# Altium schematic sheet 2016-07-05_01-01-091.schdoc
size 778 x 358 mm; SheetNumber: 1; SheetTotal: 1
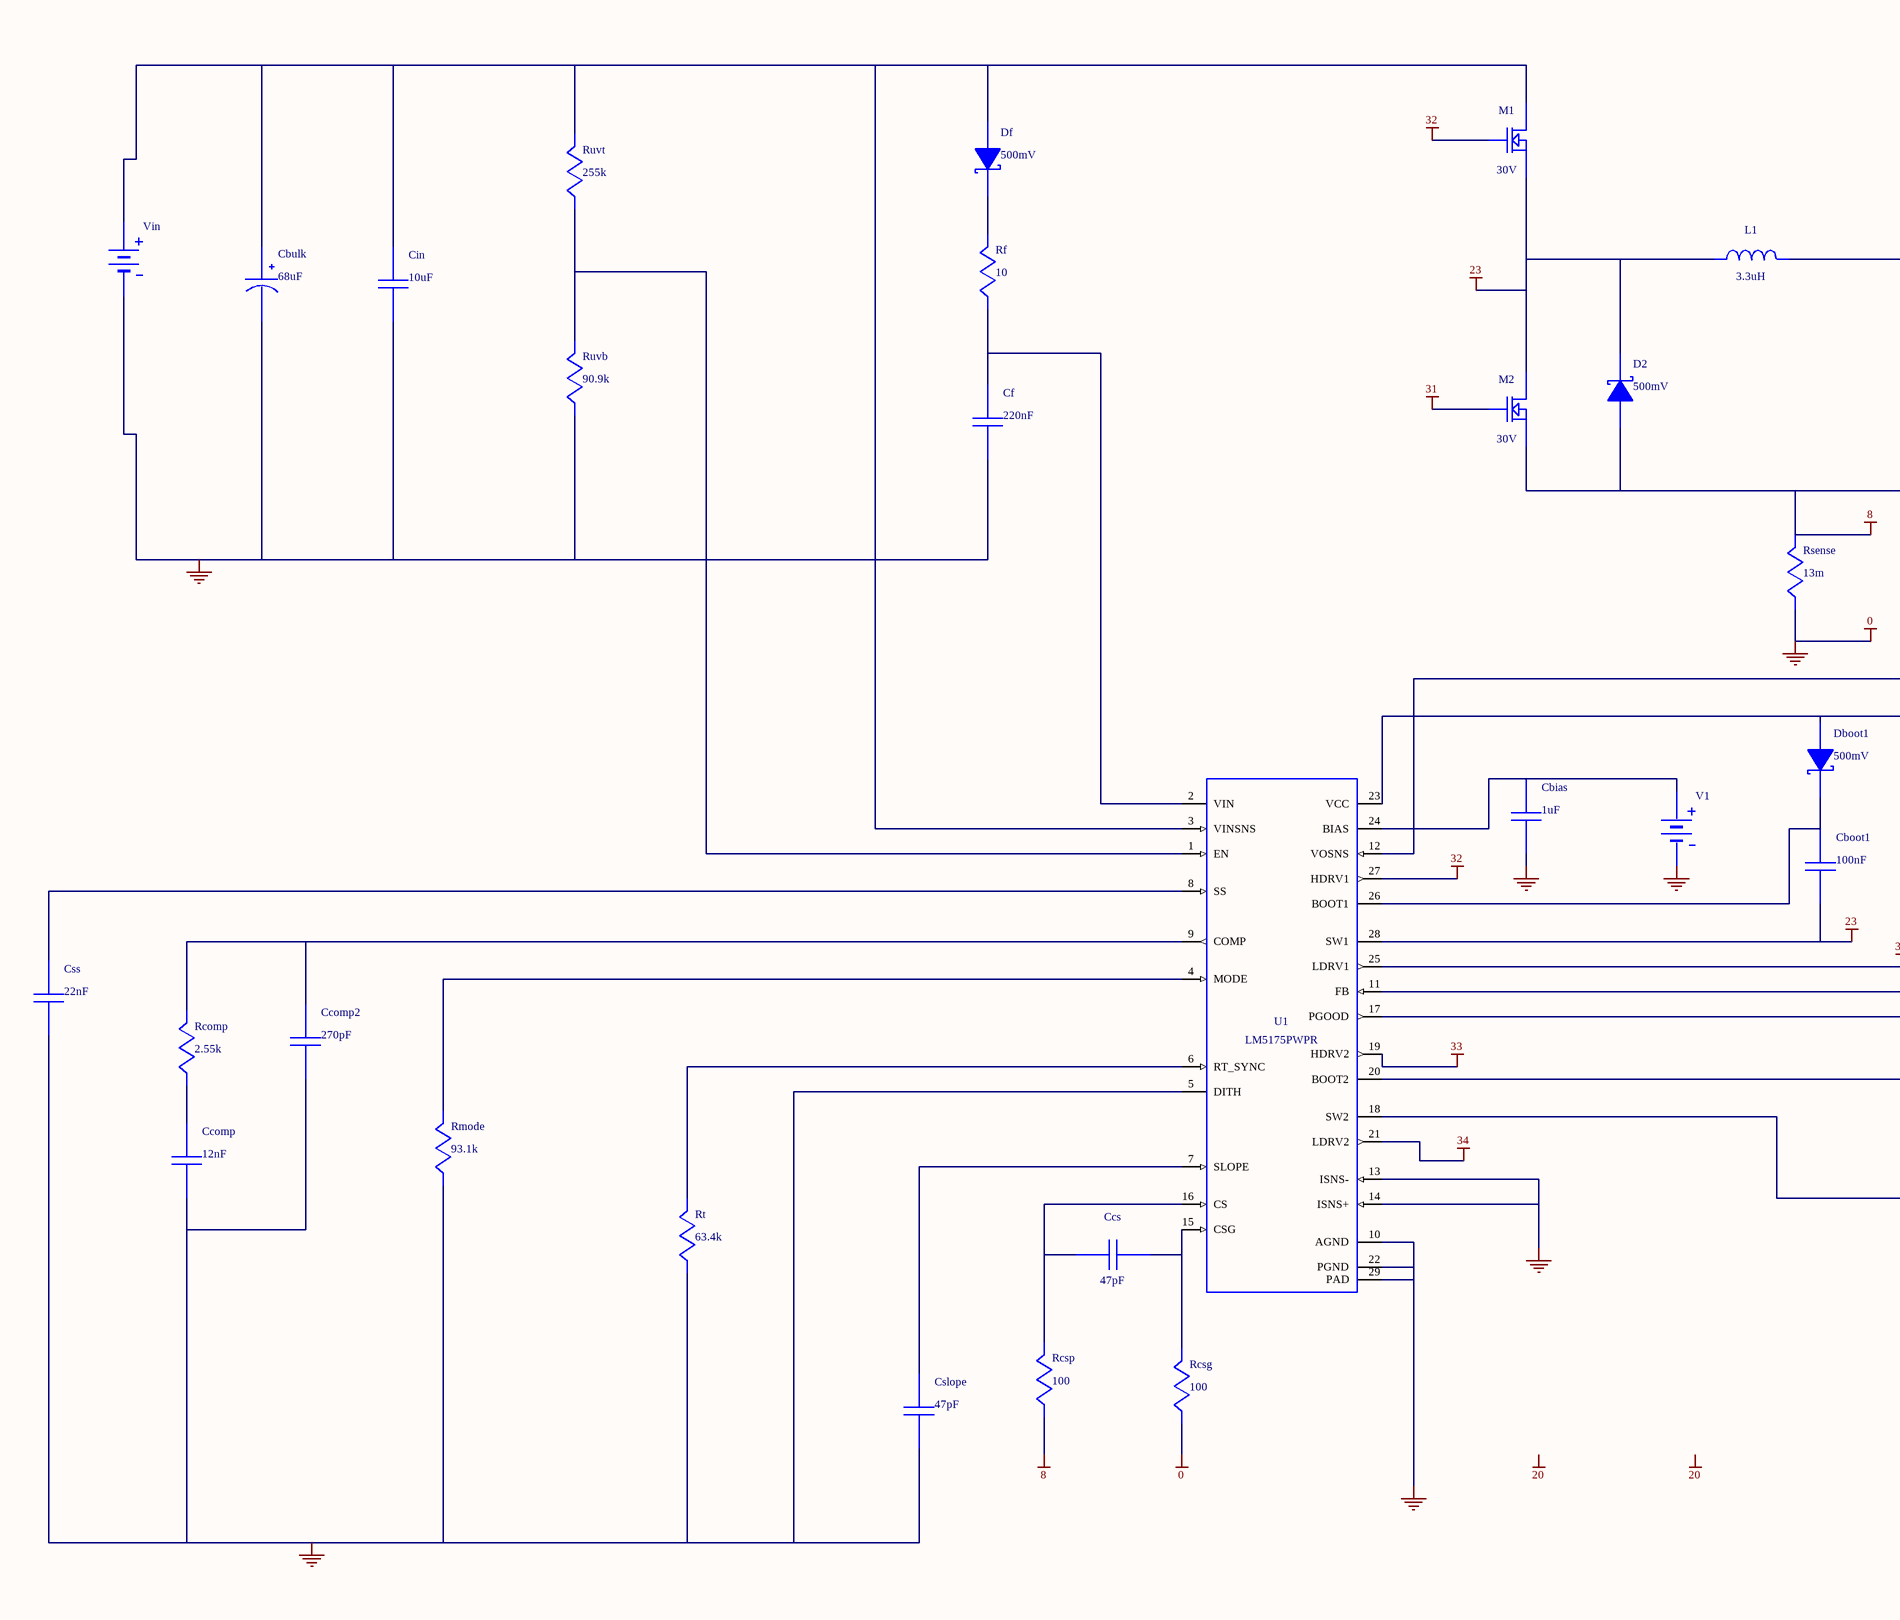
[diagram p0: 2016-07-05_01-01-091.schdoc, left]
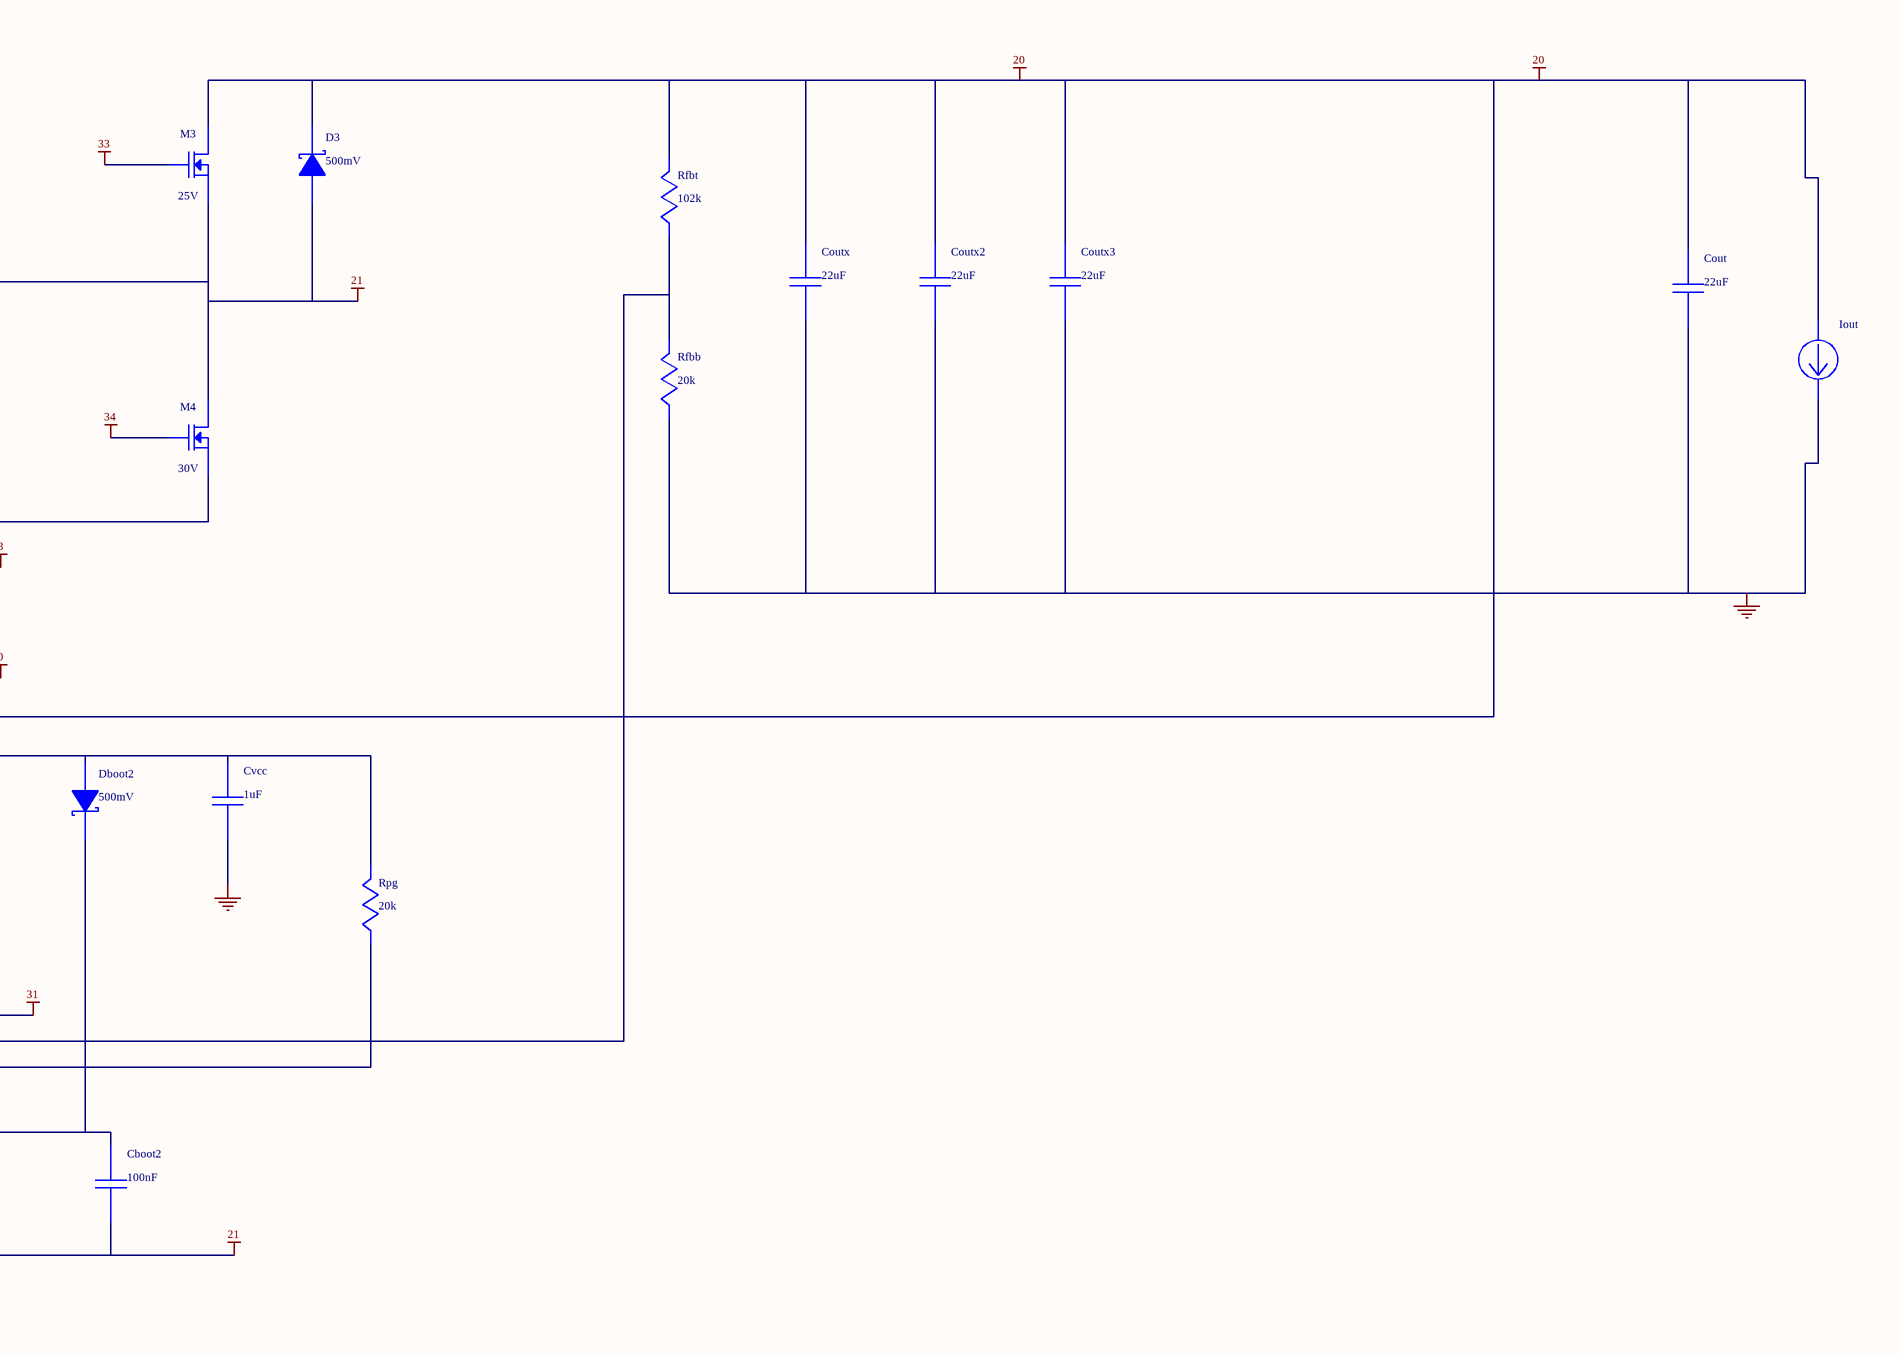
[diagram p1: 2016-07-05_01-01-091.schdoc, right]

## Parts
Cbias  value 1uF  (hidden comment: GRM188R61A105KA61D)
Cboot1  value 100nF  (hidden comment: C0603C104K3RACTU)
Cboot2  value 100nF  (hidden comment: C0603C104K3RACTU)
Cbulk  value 68uF  (hidden comment: UUD1C680MCL1GS)
Ccomp  value 12nF  (hidden comment: GRM033C80J123KE01D)
Ccomp2  value 270pF  (hidden comment: GRM033R71C271KA01D)
Ccs  value 47pF  (hidden comment: C0603C470J5GACTU)
Cf  value 220nF  (hidden comment: C0805C224K5RACTU)
Cin  value 10uF  (hidden comment: GRM21BR61C106KE15L)
Cout  value 22uF  (hidden comment: GRM21BR60J226ME39L)
Coutx  value 22uF  (hidden comment: C3225X6S1C226M)
Coutx2  value 22uF  (hidden comment: C3225X6S1C226M)
Coutx3  value 22uF  (hidden comment: C3225X6S1C226M)
Cslope  value 47pF  (hidden comment: C0603C470J5GACTU)
Css  value 22nF  (hidden comment: C0603C223K3RACTU)
Cvcc  value 1uF  (hidden comment: GRM188R61C105KA93D)
D2  value 500mV  (hidden comment: B230A-13-F)
D3  value 500mV  (hidden comment: B230A-13-F)
Dboot1  value 500mV  (hidden comment: B230A-13-F)
Dboot2  value 500mV  (hidden comment: B230A-13-F)
Df  value 500mV  (hidden comment: B230A-13-F)
Iout  WB_CURRENT_LOAD  (value not drawn)
L1  value 3.3uH  (hidden comment: SRN6045-3R3Y)
M1  value 30V  (hidden comment: CSD17579Q3A)
M2  value 30V  (hidden comment: CSD17579Q3A)
M3  value 25V  (hidden comment: CSD16323Q3)
M4  value 30V  (hidden comment: CSD17304Q3)
Rcomp  value 2.55k  (hidden comment: CRCW04022K55FKED)
Rcsg  value 100  (hidden comment: CRCW0603100RFKEA)
Rcsp  value 100  (hidden comment: CRCW0603100RFKEA)
Rf  value 10  (hidden comment: CRCW060310R0FKEA)
Rfbb  value 20k  (hidden comment: CRCW060320K0FKEA)
Rfbt  value 102k  (hidden comment: CRCW0603102KFKEA)
Rmode  value 93.1k  (hidden comment: CRCW060393K1FKEA)
Rpg  value 20k  (hidden comment: CRCW060320K0FKEA)
Rsense  value 13m  (hidden comment: PRL1632-R013-F-T1)
Rt  value 63.4k  (hidden comment: ERJ-6ENF6342V)
Ruvb  value 90.9k  (hidden comment: CRCW040290K9FKED)
Ruvt  value 255k  (hidden comment: ERJ-6ENF2553V)
U1  LM5175PWPR
V1  WB_PRIM_DC_VOLTAGE_SOURCE  (value not drawn)
Vin  WB_BATTERY  (value not drawn)

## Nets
0: Cbias.2 Cbulk.2(-) Ccomp.2 Ccomp2.2 Cf.2 Cin.2 Cout.2 Coutx.2 Coutx2.2 Coutx3.2 Cslope.2 Css.2 Cvcc.2 Iout.2(-) Rcsg.2 Rfbb.2 Rmode.2 Rsense.2 Rt.2 Ruvb.2 U1.5(DITH) U1.10(AGND) U1.13(ISNS-) U1.14(ISNS+) U1.22(PGND) U1.29(PAD) V1.2(-) Vin.2(-)
8: D2.2(A) M2.1(Source) M2.2(Source) M2.3(Source) M4.1(Source) M4.2(Source) M4.3(Source) Rcsp.2 Rsense.1
20: Cout.1 Coutx.1 Coutx2.1 Coutx3.1 D3.1(K) Iout.1(+) M3.5(Drain) M3.6(Drain) M3.7(Drain) M3.8(Drain) M3.9(Drain) Rfbt.1 U1.12(VOSNS)
21: Cboot2.2 D3.2(A) L1.2 M3.1(Source) M3.2(Source) M3.3(Source) M4.5(Drain) M4.6(Drain) M4.7(Drain) M4.8(Drain) M4.9(Drain) U1.18(SW2)
23: Cboot1.2 D2.1(K) L1.1 M1.1(Source) M1.2(Source) M1.3(Source) M2.5(Drain) M2.6(Drain) M2.7(Drain) M2.8(Drain) M2.9(Drain) U1.28(SW1)
31: M2.4(Gate) U1.25(LDRV1)
32: M1.4(Gate) U1.27(HDRV1)
33: M3.4(Gate) U1.19(HDRV2)
34: M4.4(Gate) U1.21(LDRV2)
NetCbias_1: Cbias.1 U1.24(BIAS) V1.1(+)
NetCboot1_1: Cboot1.1 Dboot1.1(K) U1.26(BOOT1)
NetCboot2_1: Cboot2.1 Dboot2.1(K) U1.20(BOOT2)
NetCbulk_1: Cbulk.1(+) Cin.1 Df.2(A) M1.5(Drain) M1.6(Drain) M1.7(Drain) M1.8(Drain) M1.9(Drain) Ruvt.1 U1.3(VINSNS) Vin.1(+)
NetCcomp2_1: Ccomp2.1 Rcomp.1 U1.9(COMP)
NetCcomp_1: Ccomp.1 Rcomp.2
NetCcs_1: Ccs.1 Rcsp.1 U1.16(CS)
NetCcs_2: Ccs.2 Rcsg.1 U1.15(CSG)
NetCf_1: Cf.1 Rf.2 U1.2(VIN)
NetCslope_1: Cslope.1 U1.7(SLOPE)
NetCss_1: Css.1 U1.8(SS)
NetCvcc_1: Cvcc.1 Dboot1.2(A) Dboot2.2(A) Rpg.1 U1.23(VCC)
NetDf_1: Df.1(K) Rf.1
NetRfbb_1: Rfbb.1 Rfbt.2 U1.11(FB)
NetRmode_1: Rmode.1 U1.4(MODE)
NetRpg_2: Rpg.2 U1.17(PGOOD)
NetRt_1: Rt.1 U1.6(RT_SYNC)
NetRuvb_1: Ruvb.1 Ruvt.2 U1.1(EN)

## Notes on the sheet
- Labels drawn without touching a wire or pin: 20

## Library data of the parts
Cbias = GRM188R61A105KA61D: GRM188R61A105KA6; Manufacturer Name: MuRata
Cboot1 Cboot2 = C0603C104K3RACTU: Manufacturer Name: Kemet
Cbulk = UUD1C680MCL1GS: Manufacturer Name: Nichicon
Ccomp = GRM033C80J123KE01D: GRM033C80J123KE0; Manufacturer Name: MuRata
Ccomp2 = GRM033R71C271KA01D: GRM033R71C271KA0; Manufacturer Name: MuRata
Ccs Cslope = C0603C470J5GACTU: Manufacturer Name: Kemet
Cf = C0805C224K5RACTU: Manufacturer Name: Kemet
Cin = GRM21BR61C106KE15L: GRM21BR61C106KE1; Manufacturer Name: MuRata
Cout = GRM21BR60J226ME39L: GRM21BR60J226ME3; Manufacturer Name: MuRata
Coutx Coutx2 Coutx3 = C3225X6S1C226M: Manufacturer Name: TDK
Css = C0603C223K3RACTU: Manufacturer Name: Kemet
Cvcc = GRM188R61C105KA93D: GRM188R61C105KA9; Manufacturer Name: MuRata
D2 D3 Dboot1 Dboot2 Df = B230A-13-F: Manufacturer Name: Diodes Inc.
L1 = SRN6045-3R3Y: Manufacturer Name: Bourns
M1 M2 = CSD17579Q3A: Manufacturer Name: Texas Instruments
M3 = CSD16323Q3: Manufacturer Name: Texas Instruments
M4 = CSD17304Q3: Manufacturer Name: Texas Instruments
Rcomp = CRCW04022K55FKED: Manufacturer Name: Vishay-Dale
Rcsg Rcsp = CRCW0603100RFKEA: Manufacturer Name: Vishay-Dale
Rf = CRCW060310R0FKEA: Manufacturer Name: Vishay-Dale
Rfbb Rpg = CRCW060320K0FKEA: Manufacturer Name: Vishay-Dale
Rfbt = CRCW0603102KFKEA: Manufacturer Name: Vishay-Dale
Rmode = CRCW060393K1FKEA: Manufacturer Name: Vishay-Dale
Rsense = PRL1632-R013-F-T1: PRL1632-R013-F-T; Manufacturer Name: Susumu Co Ltd
Rt = ERJ-6ENF6342V: Manufacturer Name: Panasonic
Ruvb = CRCW040290K9FKED: Manufacturer Name: Vishay-Dale
Ruvt = ERJ-6ENF2553V: Manufacturer Name: Panasonic
U1 = LM5175PWPR: Manufacturer Name: Texas Instruments
V1 = WB_PRIM_DC_VOLTAGE_SOURCE: WB_PRIM_DC_VOLTA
